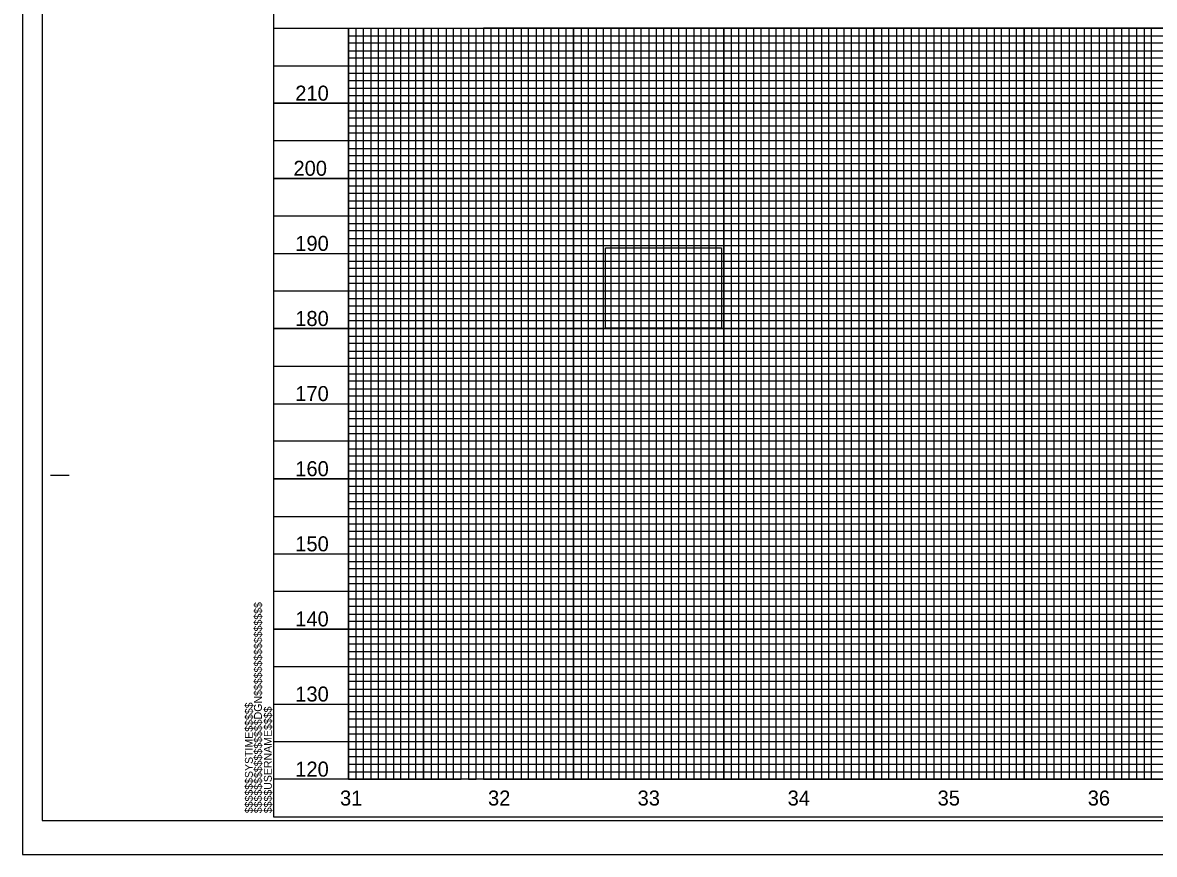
# Model space of a CAD drawing. Extents: x 1779926 to 1781610, y 620464 to 621564.
# Drawn here: x 1779926 to 1780680, y 620464 to 621018 of the extents above; entities that cross this region are included whole.
import ezdxf

# ---------------------------------------------------------------- set-up
doc = ezdxf.new("R2010")
doc.units = 0
for name, color, linetype in [('Exist Vertical Profile Horizontal Axis Label Major', 7, 'Continuous'), ('Exist Vertical Profile Vertical Axis Label', 7, 'Continuous'), ('Prop Grid Mask', 7, 'Continuous'), ('Scratch_Level_0', 7, 'Continuous'), ('Sheet Cutting Line CELL', 7, 'Continuous'), ('Sheet DOT Grid CELL', 7, 'Continuous'), ('Sheet Layout Profile Border Port 2', 7, 'Continuous'), ('Sheet Plot Border Inside CELL', 7, 'Continuous'), ('Sheet Plot Border Outside CELL', 7, 'Continuous'), ('Sheet Profile CELL', 7, 'Continuous'), ('Sheet Profile Grid Major CELL', 7, 'Continuous'), ('Sheet Profile Grid Middle CELL', 7, 'Continuous'), ('Sheet Profile Grid Minor CELL', 7, 'Continuous')]:
    doc.layers.add(name, color=color, linetype=linetype)

msp = doc.modelspace()

# ---------------------------------------------------------------- linework, layer by layer
at = {"layer": 'Prop Grid Mask'}
msp.add_lwpolyline([(1780314.2, 620867.86), (1780391.53, 620867.86), (1780391.53, 620814.45), (1780314.2, 620814.45)], close=True, dxfattribs=at)
at = {"layer": 'Scratch_Level_0'}
msp.add_lwpolyline([(1780142.96, 620514.19), (1780142.96, 621014.19), (1781542.96, 621014.19), (1781542.96, 620514.19)], close=True, dxfattribs=at)
at = {"layer": 'Sheet Cutting Line CELL'}
for p, q in [((1779925.96, 621564.19), (1779925.96, 620464.19)), ((1779925.96, 620464.19), (1781609.96, 620464.19))]:
    msp.add_line(p, q, dxfattribs=at)
at = {"layer": 'Sheet DOT Grid CELL'}
for p, q in [((1780092.96, 621014.19), (1781592.85, 621014.19)), ((1780142.96, 621014.19), (1780142.96, 620514.19)), ((1780192.96, 621014.19), (1780192.96, 620514.19)), ((1780242.96, 621014.19), (1780242.96, 620514.19)), ((1780292.96, 621014.19), (1780292.96, 620514.19)), ((1780342.96, 621014.19), (1780342.96, 620514.19)), ((1780392.96, 621014.19), (1780392.96, 620514.19)), ((1780442.96, 621014.19), (1780442.96, 620514.19)), ((1780492.96, 621014.19), (1780492.96, 620514.19)), ((1780542.96, 621014.19), (1780542.96, 620514.19)), ((1780592.96, 621014.19), (1780592.96, 620514.19)), ((1780642.96, 621014.19), (1780642.96, 620514.19)), ((1780092.96, 620964.19), (1781592.85, 620964.19)), ((1780092.96, 620914.19), (1781592.85, 620914.19)), ((1780092.96, 620864.19), (1781592.85, 620864.19)), ((1780092.96, 620814.19), (1781592.85, 620814.19)), ((1780092.96, 620764.19), (1781592.85, 620764.19)), ((1780092.96, 620714.19), (1781592.85, 620714.19)), ((1780092.96, 620664.19), (1781592.85, 620664.19)), ((1780092.96, 620614.19), (1781592.85, 620614.19)), ((1780092.96, 620564.19), (1781592.85, 620564.19))]:
    msp.add_line(p, q, dxfattribs=at)
at = {"layer": 'Sheet Layout Profile Border Port 2'}
for points in [[(1780142.96, 621014.19), (1781542.96, 621014.19), (1781542.96, 620514.19), (1780142.96, 620514.19)], [(1781542.96, 621014.19), (1780232.96, 621014.19), (1780232.96, 620514.19), (1781542.96, 620514.19)]]:
    msp.add_lwpolyline(points, close=True, dxfattribs=at)
at = {"layer": 'Sheet Plot Border Inside CELL'}
msp.add_lwpolyline([(1779938.96, 620486.64), (1781605.46, 620486.64), (1781605.46, 621541.74), (1779938.96, 621541.74)], close=True, dxfattribs=at)
at = {"layer": 'Sheet Plot Border Outside CELL'}
msp.add_lwpolyline([(1779925.96, 620464.19), (1781609.96, 620464.19), (1781609.96, 621564.19), (1779925.96, 621564.19)], close=True, dxfattribs=at)
at = {"layer": 'Sheet Profile CELL'}
for p, q in [((1780092.96, 621014.19), (1781592.96, 621014.19)), ((1779944.46, 620716.69), (1779956.96, 620716.69)), ((1781592.96, 620514.19), (1780092.96, 620514.19)), ((1780092.96, 620489.19), (1781592.96, 620489.19)), ((1780092.96, 620489.19), (1780092.96, 620489.19)), ((1780092.96, 620489.19), (1780092.96, 620489.19)), ((1780092.96, 620489.19), (1780092.96, 620489.19)), ((1780092.96, 620489.19), (1780092.96, 620489.19)), ((1780092.96, 620489.19), (1780092.96, 620489.19)), ((1780092.96, 620489.19), (1780092.96, 620489.19)), ((1780092.96, 620489.19), (1780092.96, 620489.19))]:
    msp.add_line(p, q, dxfattribs=at)
msp.add_lwpolyline([(1781592.96, 621539.19), (1780092.96, 621539.19), (1780092.96, 620489.19), (1781592.96, 620489.19)], close=True, dxfattribs=at)
msp.add_lwpolyline([(1780130.46, 620489.19), (1780130.46, 620489.19)], dxfattribs=at)
at = {"layer": 'Sheet Profile Grid Major CELL'}
for p, q in [((1780592.96, 621014.19), (1780642.96, 621014.19)), ((1780092.96, 620514.19), (1780092.96, 620514.19))]:
    msp.add_line(p, q, dxfattribs=at)
for points in [[(1780142.96, 621014.19), (1780142.96, 620514.19), (1780192.96, 620514.19), (1780192.96, 621014.19), (1780242.96, 621014.19), (1780242.96, 620514.19), (1780292.96, 620514.19), (1780292.96, 621014.19), (1780342.96, 621014.19), (1780342.96, 620514.19), (1780392.96, 620514.19), (1780392.96, 621014.19), (1780442.96, 621014.19), (1780442.96, 620514.19), (1780492.96, 620514.19), (1780492.96, 621014.19), (1780542.96, 621014.19), (1780542.96, 620514.19), (1780592.96, 620514.19), (1780592.96, 621014.19), (1780642.96, 621014.19), (1780642.96, 620514.19), (1780692.96, 620514.19)], [(1781592.96, 620964.19), (1780092.96, 620964.19)], [(1781592.96, 620914.19), (1780092.96, 620914.19), (1780092.96, 620864.19), (1781592.96, 620864.19)], [(1781592.96, 620814.19), (1780092.96, 620814.19), (1780092.96, 620764.19), (1781592.96, 620764.19)], [(1781592.96, 620714.19), (1780092.96, 620714.19), (1780092.96, 620664.19), (1781592.96, 620664.19)], [(1781592.96, 620614.19), (1780092.96, 620614.19), (1780092.96, 620614.19), (1780092.96, 620564.19), (1781592.96, 620564.19)], [(1781592.96, 620514.19), (1780092.96, 620514.19)]]:
    msp.add_lwpolyline(points, dxfattribs=at)
at = {"layer": 'Sheet Profile Grid Middle CELL'}
for points in [[(1780117.96, 621014.19), (1780167.96, 621014.19), (1780167.96, 620514.19), (1780217.96, 620514.19), (1780217.96, 621014.19), (1780267.96, 621014.19), (1780267.96, 620514.19), (1780317.96, 620514.19), (1780317.96, 621014.19), (1780367.96, 621014.19), (1780367.96, 620514.19), (1780417.96, 620514.19), (1780417.96, 621014.19), (1780467.96, 621014.19), (1780467.96, 620514.19), (1780517.96, 620514.19), (1780517.96, 621014.19), (1780567.96, 621014.19), (1780567.96, 620514.19), (1780617.96, 620514.19), (1780617.96, 621014.19), (1780667.96, 621014.19), (1780667.96, 620514.19), (1780717.96, 620514.19)], [(1780092.96, 620989.19), (1781592.96, 620989.19)], [(1781592.96, 620939.19), (1780092.96, 620939.19), (1780092.96, 620889.19), (1781592.96, 620889.19)], [(1781592.96, 620839.19), (1780092.96, 620839.19), (1780092.96, 620789.19), (1781592.96, 620789.19)], [(1781592.96, 620739.19), (1780092.96, 620739.19), (1780092.96, 620689.19), (1781592.96, 620689.19)], [(1781592.96, 620639.19), (1780092.96, 620639.19), (1780092.96, 620589.19), (1781592.96, 620589.19)], [(1781592.96, 620539.19), (1780092.96, 620539.19)]]:
    msp.add_lwpolyline(points, dxfattribs=at)
at = {"layer": 'Sheet Profile Grid Minor CELL'}
for p, q in [((1780142.96, 621009.19), (1781542.96, 621009.19)), ((1781542.96, 621004.19), (1780142.96, 621004.19)), ((1780142.96, 620999.19), (1781542.96, 620999.19)), ((1781542.96, 620994.19), (1780142.96, 620994.19)), ((1780142.96, 620984.19), (1781542.96, 620984.19)), ((1781542.96, 620979.19), (1780142.96, 620979.19)), ((1780142.96, 620974.19), (1781542.96, 620974.19)), ((1781542.96, 620969.19), (1780142.96, 620969.19)), ((1780142.96, 620959.19), (1781542.96, 620959.19)), ((1781542.96, 620954.19), (1780142.96, 620954.19)), ((1780142.96, 620949.19), (1781542.96, 620949.19)), ((1781542.96, 620944.19), (1780142.96, 620944.19)), ((1780142.96, 620934.19), (1781542.96, 620934.19)), ((1781542.96, 620929.19), (1780142.96, 620929.19)), ((1780142.96, 620924.19), (1781542.96, 620924.19)), ((1781542.96, 620919.19), (1780142.96, 620919.19)), ((1780142.96, 620909.19), (1781542.96, 620909.19)), ((1781542.96, 620904.19), (1780142.96, 620904.19)), ((1780142.96, 620899.19), (1781542.96, 620899.19)), ((1781542.96, 620894.19), (1780142.96, 620894.19)), ((1780142.96, 620884.19), (1781542.96, 620884.19)), ((1781542.96, 620879.19), (1780142.96, 620879.19)), ((1780142.96, 620874.19), (1781542.96, 620874.19)), ((1781542.96, 620869.19), (1780142.96, 620869.19)), ((1780142.96, 620859.19), (1781542.96, 620859.19)), ((1781542.96, 620854.19), (1780142.96, 620854.19)), ((1780142.96, 620849.19), (1781542.96, 620849.19)), ((1781542.96, 620844.19), (1780142.96, 620844.19)), ((1780142.96, 620834.19), (1781542.96, 620834.19)), ((1781542.96, 620829.19), (1780142.96, 620829.19)), ((1780142.96, 620824.19), (1781542.96, 620824.19)), ((1781542.96, 620819.19), (1780142.96, 620819.34)), ((1780142.96, 620809.19), (1781542.96, 620809.19)), ((1781542.96, 620804.19), (1780142.96, 620804.19)), ((1780142.96, 620799.19), (1781542.96, 620799.19)), ((1781542.96, 620794.19), (1780142.96, 620794.19)), ((1780142.96, 620784.19), (1781542.96, 620784.19)), ((1781542.96, 620779.19), (1780142.96, 620779.19)), ((1780142.96, 620774.19), (1781542.96, 620774.19)), ((1781542.96, 620769.19), (1780142.96, 620769.19)), ((1780142.96, 620759.19), (1781542.96, 620759.19)), ((1781542.96, 620754.19), (1780142.96, 620754.19)), ((1780142.96, 620749.19), (1781542.96, 620749.19)), ((1781542.96, 620744.19), (1780142.96, 620744.19)), ((1780142.96, 620734.19), (1781542.96, 620734.19)), ((1781542.96, 620729.19), (1780142.96, 620729.19)), ((1780142.96, 620724.19), (1781542.96, 620724.19)), ((1781542.96, 620719.19), (1780142.96, 620719.19)), ((1780142.96, 620709.19), (1781542.96, 620709.19)), ((1781542.96, 620704.19), (1780142.96, 620704.19)), ((1780142.96, 620699.19), (1781542.96, 620699.19)), ((1781542.96, 620694.19), (1780142.96, 620694.19)), ((1780142.96, 620684.19), (1781542.96, 620684.19)), ((1781542.96, 620679.19), (1780142.96, 620679.19)), ((1780142.96, 620674.19), (1781542.96, 620674.19)), ((1781542.96, 620669.19), (1780142.96, 620669.19)), ((1780142.96, 620659.19), (1781542.96, 620659.19)), ((1781542.96, 620654.19), (1780142.96, 620654.19)), ((1780142.96, 620649.19), (1781542.96, 620649.19)), ((1781542.96, 620644.19), (1780142.96, 620644.19)), ((1780142.96, 620634.19), (1781542.96, 620634.19)), ((1781542.96, 620629.19), (1780142.96, 620629.19)), ((1780142.96, 620624.19), (1781542.96, 620624.19)), ((1781542.96, 620619.19), (1780142.96, 620619.19)), ((1780142.96, 620609.19), (1781542.96, 620609.19)), ((1781542.96, 620604.19), (1780142.96, 620604.19)), ((1780142.96, 620599.19), (1781542.96, 620599.19)), ((1781542.96, 620594.19), (1780142.96, 620594.19)), ((1780142.96, 620584.19), (1781542.96, 620584.19)), ((1781542.96, 620579.19), (1780142.96, 620579.19)), ((1780142.96, 620574.19), (1781542.96, 620574.19)), ((1781542.96, 620569.19), (1780142.96, 620569.19)), ((1780142.96, 620559.19), (1781542.96, 620559.19)), ((1781542.96, 620554.19), (1780142.96, 620554.19)), ((1780142.96, 620549.19), (1781542.96, 620549.19)), ((1781542.96, 620544.19), (1780142.96, 620544.19)), ((1780142.96, 620534.19), (1781542.96, 620534.19)), ((1781542.96, 620529.19), (1780142.96, 620529.19)), ((1780142.96, 620524.19), (1781542.96, 620524.19)), ((1780142.96, 620519.19), (1781542.96, 620519.19))]:
    msp.add_line(p, q, dxfattribs=at)
for points in [[(1780142.96, 621014.19), (1780147.96, 621014.19), (1780147.96, 620514.19), (1780152.96, 620514.19), (1780152.96, 621014.19), (1780157.96, 621014.19), (1780157.96, 620514.19), (1780162.96, 620514.19), (1780162.96, 621014.19), (1780172.96, 621014.19), (1780172.96, 620514.19), (1780177.96, 620514.19), (1780177.96, 621014.19), (1780182.96, 621014.19), (1780182.96, 620514.19), (1780187.96, 620514.19), (1780197.96, 620514.19), (1780202.96, 620514.19), (1780202.96, 621014.19), (1780207.96, 621014.19), (1780207.96, 620514.19), (1780212.96, 620514.19), (1780212.96, 621014.19), (1780222.96, 621014.19), (1780222.96, 620514.19), (1780227.96, 620514.19), (1780227.96, 621014.19), (1780232.96, 621014.19), (1780232.96, 620514.19), (1780237.96, 620514.19), (1780237.96, 621014.19), (1780247.96, 621014.19), (1780247.96, 620514.19), (1780252.96, 620514.19), (1780252.96, 621014.19), (1780257.96, 621014.19), (1780257.96, 620514.19), (1780262.96, 620514.19), (1780262.96, 621014.19), (1780272.96, 621014.19), (1780272.96, 620514.19), (1780277.96, 620514.19), (1780277.96, 621014.19), (1780282.96, 621014.19), (1780282.96, 620514.19), (1780287.96, 620514.19), (1780287.96, 621014.19), (1780297.96, 621014.19), (1780297.96, 620514.19), (1780302.96, 620514.19), (1780302.96, 621014.19), (1780307.96, 621014.19), (1780307.96, 620514.19), (1780312.96, 620514.19), (1780312.96, 621014.19), (1780322.96, 621014.19), (1780322.96, 620514.19), (1780327.96, 620514.19), (1780327.96, 621014.19), (1780332.96, 621014.19), (1780332.96, 620514.19), (1780337.96, 620514.19), (1780337.96, 621014.19), (1780347.96, 621014.19), (1780347.96, 620514.19), (1780352.96, 620514.19), (1780352.96, 621014.19), (1780357.96, 621014.19), (1780357.96, 620514.19)], [(1780187.96, 620514.19), (1780187.96, 621014.19), (1780197.96, 621014.19), (1780197.96, 620514.19)], [(1780357.96, 620514.19), (1780362.96, 620514.19), (1780362.96, 621014.19), (1780372.96, 621014.19), (1780372.96, 620514.19), (1780377.96, 620514.19), (1780377.96, 621014.19), (1780382.96, 621014.19), (1780382.96, 620514.19), (1780387.96, 620514.19), (1780387.96, 621014.19), (1780397.96, 621014.19), (1780397.96, 620514.19), (1780402.96, 620514.19), (1780402.96, 621014.19), (1780407.96, 621014.19), (1780407.96, 620514.19), (1780412.96, 620514.19), (1780412.96, 621014.19), (1780422.96, 621014.19), (1780422.96, 620514.19), (1780427.96, 620514.19), (1780427.96, 621014.19), (1780432.96, 621014.19), (1780432.96, 620514.19), (1780437.96, 620514.19), (1780437.96, 621014.19), (1780447.96, 621014.19), (1780447.96, 620514.19), (1780452.96, 620514.19), (1780452.96, 621014.19), (1780457.96, 621014.19), (1780457.96, 620514.19), (1780462.96, 620514.19), (1780462.96, 621014.19), (1780472.96, 621014.19), (1780472.96, 620514.19), (1780477.96, 620514.19), (1780477.96, 621014.19), (1780482.96, 621014.19), (1780482.96, 620514.19), (1780487.96, 620514.19), (1780487.96, 621014.19), (1780497.96, 621014.19), (1780497.96, 620514.19), (1780502.96, 620514.19), (1780502.96, 621014.19), (1780507.96, 621014.19), (1780507.96, 620514.19), (1780512.96, 620514.19), (1780512.96, 621014.19), (1780522.96, 621014.19), (1780522.96, 620514.19), (1780527.96, 620514.19), (1780527.96, 621014.19), (1780532.96, 621014.19), (1780532.96, 620514.19), (1780537.96, 620514.19), (1780537.96, 621014.19), (1780547.96, 621014.19), (1780547.96, 620514.19), (1780552.96, 620514.19), (1780552.96, 621014.19), (1780557.96, 621014.19), (1780557.96, 620514.19), (1780562.96, 620514.19), (1780562.96, 621014.19), (1780572.96, 621014.19), (1780572.96, 620514.19), (1780577.96, 620514.19), (1780577.96, 621014.19), (1780582.96, 621014.19), (1780582.96, 620514.19), (1780587.96, 620514.19), (1780587.96, 621014.19), (1780597.96, 621014.19), (1780597.96, 620514.19), (1780602.96, 620514.19), (1780602.96, 621014.19), (1780607.96, 621014.19), (1780607.96, 620514.19), (1780612.96, 620514.19), (1780612.96, 621014.19), (1780622.96, 621014.19), (1780622.96, 620514.19), (1780627.96, 620514.19), (1780627.96, 621014.19), (1780632.96, 621014.19), (1780632.96, 620514.19), (1780637.96, 620514.19), (1780637.96, 621014.19), (1780647.96, 621014.19), (1780647.96, 620514.19), (1780652.96, 620514.19), (1780652.96, 621014.19), (1780657.96, 621014.19), (1780657.96, 620514.19), (1780662.96, 620514.19), (1780662.96, 621014.19), (1780672.96, 621014.19)], [(1780672.96, 621014.19), (1780672.96, 620514.19), (1780677.96, 620514.19), (1780677.96, 621014.19), (1780682.96, 621014.19)]]:
    msp.add_lwpolyline(points, dxfattribs=at)

# ---------------------------------------------------------------- texts
at = {"layer": 'Exist Vertical Profile Horizontal Axis Label Major'}
for s, p in [('31', (1780137.36, 620496.69)), ('32', (1780235.93, 620496.69)), ('33', (1780335.57, 620496.69)), ('34', (1780435.49, 620496.69)), ('35', (1780535.39, 620496.69)), ('36', (1780635.38, 620496.69))]:
    msp.add_text(s, height=10, dxfattribs=at).set_placement(p)
at = {"layer": 'Exist Vertical Profile Vertical Axis Label'}
for s, p in [('210', (1780107.55, 620965.93)), ('200', (1780106.36, 620915.93)), ('190', (1780107.55, 620865.93)), ('180', (1780107.55, 620815.93)), ('170', (1780107.55, 620765.93)), ('160', (1780107.55, 620715.93)), ('150', (1780107.55, 620665.93)), ('140', (1780107.55, 620615.93)), ('130', (1780107.55, 620565.93)), ('120', (1780107.55, 620515.93))]:
    msp.add_text(s, height=10, dxfattribs=at).set_placement(p)
at = {"layer": 'Sheet Profile CELL'}
for s, p in [('$$$$$$$$$$$$$$$$DGN$$$$$$$$$$$$$$$$', (1780085.32, 620491.57)), ('$$$$$$SYSTIME$$$$$', (1780079.27, 620491.57)), ('$$$$USERNAME$$$$', (1780091.9, 620491.58))]:
    msp.add_text(s, height=5.25, rotation=90, dxfattribs=at).set_placement(p)

doc.saveas('drawing.dxf')
